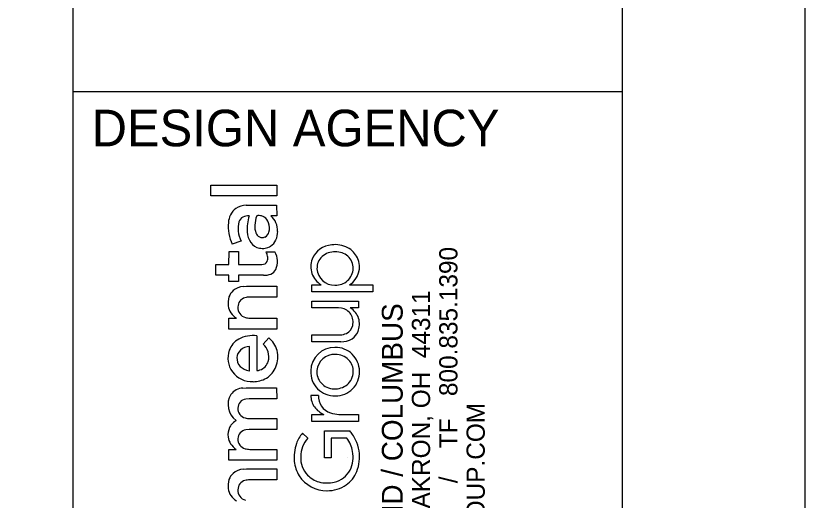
# Model space of a CAD drawing. Extents: x -0.5 to 34, y 0 to 22.
# Drawn here: x 31.843 to 34, y 3.382 to 4.707 of the extents above; entities that cross this region are included whole.
import ezdxf

# ---------------------------------------------------------------- set-up
doc = ezdxf.new("R2010")
doc.units = 0
for name, color, linetype in [('PM_X_CL_Double_Solid', 7, 'Continuous'), ('PM_X_Edge_Line', 7, 'Continuous'), ('PM_X_Transverse_Line', 7, 'Continuous')]:
    doc.layers.add(name, color=color, linetype=linetype)

msp = doc.modelspace()

# ---------------------------------------------------------------- linework, layer by layer
at = {"layer": 'PM_X_CL_Double_Solid'}
for p, q in [((32.3756, 4.2141), (32.3756, 4.244)), ((32.3756, 4.244), (32.5557, 4.244)), ((32.5557, 4.244), (32.5557, 4.2141)), ((32.5557, 4.2141), (32.3756, 4.2141)), ((32.4727, 4.189), (32.5555, 4.1892)), ((32.5555, 4.1892), (32.5557, 4.1596)), ((32.5557, 4.1596), (32.5397, 4.1596)), ((32.4582, 4.0904), (32.4343, 4.0823)), ((32.4254, 4.027), (32.4255, 4.0621)), ((32.4255, 4.0621), (32.4511, 4.0621)), ((32.4511, 4.0621), (32.4512, 4.027)), ((32.527, 4.0616), (32.5511, 4.0616)), ((32.3896, 3.9972), (32.3896, 4.027)), ((32.3896, 4.027), (32.4254, 4.027)), ((32.4512, 4.027), (32.515, 4.027)), ((32.515, 4.027), (32.52, 4.0275)), ((32.4254, 3.9972), (32.3896, 3.9972)), ((32.4254, 3.9807), (32.4254, 3.9972)), ((32.5197, 3.9972), (32.4511, 3.9972)), ((32.4511, 3.9972), (32.4511, 3.9807)), ((32.4511, 3.9807), (32.4254, 3.9807)), ((32.6515, 3.9521), (32.6515, 3.9711)), ((32.6515, 3.9711), (32.6771, 3.9711)), ((32.7549, 3.9713), (32.8186, 3.9711)), ((32.8186, 3.9711), (32.8184, 3.9521)), ((32.4644, 3.9669), (32.4729, 3.9673)), ((32.4729, 3.9673), (32.5557, 3.9673)), ((32.5557, 3.9673), (32.5557, 3.9375)), ((32.8184, 3.9521), (32.6515, 3.9521)), ((32.5557, 3.9375), (32.4814, 3.9375)), ((32.6515, 3.908), (32.6515, 3.9267)), ((32.6515, 3.9267), (32.7791, 3.9266)), ((32.7791, 3.9266), (32.7791, 3.908)), ((32.7249, 3.908), (32.6515, 3.908)), ((32.7328, 3.9073), (32.7249, 3.908)), ((32.7791, 3.908), (32.7569, 3.908)), ((32.4254, 3.8503), (32.4254, 3.8802)), ((32.4254, 3.8802), (32.4455, 3.8802)), ((32.4822, 3.8802), (32.5557, 3.8802)), ((32.5557, 3.8802), (32.5557, 3.8504)), ((32.5557, 3.8504), (32.4254, 3.8503)), ((32.5011, 3.8321), (32.5012, 3.7366)), ((32.5188, 3.8093), (32.5342, 3.8266)), ((32.6515, 3.8344), (32.7291, 3.8345)), ((32.6517, 3.8154), (32.6515, 3.8344)), ((32.4814, 3.7364), (32.4814, 3.803)), ((32.7307, 3.8154), (32.6517, 3.8154)), ((32.4802, 3.7363), (32.4814, 3.7364)), ((32.4633, 3.6891), (32.4726, 3.6897)), ((32.4726, 3.6897), (32.5556, 3.6897)), ((32.5556, 3.6897), (32.5557, 3.6598)), ((32.6493, 3.6691), (32.6698, 3.6691)), ((32.4806, 3.6598), (32.471, 3.6588)), ((32.5557, 3.6598), (32.4806, 3.6598)), ((32.4822, 3.6055), (32.5557, 3.6055)), ((32.5557, 3.6055), (32.5557, 3.5757)), ((32.6515, 3.598), (32.6515, 3.617)), ((32.6515, 3.617), (32.6848, 3.617)), ((32.726, 3.617), (32.7791, 3.617)), ((32.7791, 3.617), (32.779, 3.598)), ((32.4444, 3.5992), (32.4446, 3.6007)), ((32.779, 3.598), (32.6515, 3.598)), ((32.4809, 3.5757), (32.4714, 3.5747)), ((32.5557, 3.5757), (32.4809, 3.5757)), ((32.6264, 3.5655), (32.6411, 3.5524)), ((32.6868, 3.5718), (32.7552, 3.5719)), ((32.6868, 3.4978), (32.6868, 3.5718)), ((32.7045, 3.5524), (32.7043, 3.4978)), ((32.7474, 3.5523), (32.7045, 3.5524)), ((32.4254, 3.4915), (32.4254, 3.5214)), ((32.4254, 3.5214), (32.4451, 3.5214)), ((32.4821, 3.5214), (32.5557, 3.5214)), ((32.5557, 3.5214), (32.5557, 3.4916)), ((32.7043, 3.4978), (32.6868, 3.4978)), ((32.75, 3.5), (32.75, 3.5)), ((32.5557, 3.4916), (32.4254, 3.4915)), ((32.4644, 3.4674), (32.4729, 3.4678)), ((32.4729, 3.4678), (32.5557, 3.4678)), ((32.5557, 3.4678), (32.5557, 3.438)), ((32.5557, 3.438), (32.4814, 3.438))]:
    msp.add_line(p, q, dxfattribs=at)
msp.add_lwpolyline([(32.3756, 4.2141), (32.3756, 4.244), (32.5557, 4.244), (32.5557, 4.2141)], close=True, dxfattribs=at)
for points in [[(32.4727, 4.189), (32.5555, 4.1892), (32.5557, 4.1596)], [(32.5557, 4.1596), (32.5397, 4.1596)], [(32.4582, 4.0904), (32.4343, 4.0823)], [(32.5197, 3.9972), (32.4511, 3.9972), (32.4511, 3.9807), (32.4254, 3.9807), (32.4254, 3.9972), (32.3896, 3.9972), (32.3896, 4.027), (32.4254, 4.027), (32.4255, 4.0621), (32.4511, 4.0621), (32.4512, 4.027), (32.515, 4.027), (32.52, 4.0275)], [(32.527, 4.0616), (32.5511, 4.0616)], [(32.7549, 3.9713), (32.8186, 3.9711), (32.8184, 3.9521), (32.6515, 3.9521)], [(32.6515, 3.9521), (32.6515, 3.9711), (32.6771, 3.9711)], [(32.4644, 3.9669), (32.4729, 3.9673), (32.5557, 3.9673), (32.5557, 3.9375), (32.4814, 3.9375)], [(32.7328, 3.9073), (32.7249, 3.908), (32.6515, 3.908), (32.6515, 3.9267), (32.7791, 3.9266), (32.7791, 3.908), (32.7569, 3.908)], [(32.4254, 3.8503), (32.4254, 3.8802), (32.4455, 3.8802)], [(32.4822, 3.8802), (32.5557, 3.8802), (32.5557, 3.8504), (32.4254, 3.8503)], [(32.5011, 3.8321), (32.5012, 3.7366)], [(32.5188, 3.8093), (32.5342, 3.8266)], [(32.7307, 3.8154), (32.6517, 3.8154), (32.6515, 3.8344), (32.7291, 3.8345)], [(32.4802, 3.7363), (32.4814, 3.7364), (32.4814, 3.803)], [(32.4633, 3.6891), (32.4726, 3.6897), (32.5556, 3.6897), (32.5557, 3.6598), (32.4806, 3.6598), (32.471, 3.6588)], [(32.6493, 3.6691), (32.6698, 3.6691)], [(32.4822, 3.6055), (32.5557, 3.6055), (32.5557, 3.5757), (32.4809, 3.5757), (32.4714, 3.5747)], [(32.6515, 3.598), (32.6515, 3.617), (32.6848, 3.617)], [(32.726, 3.617), (32.7791, 3.617), (32.779, 3.598), (32.6515, 3.598)], [(32.4444, 3.5992), (32.4446, 3.6007)], [(32.6264, 3.5655), (32.6411, 3.5524)], [(32.7474, 3.5523), (32.7045, 3.5524), (32.7043, 3.4978), (32.6868, 3.4978), (32.6868, 3.5718), (32.7552, 3.5719)], [(32.4254, 3.4915), (32.4254, 3.5214), (32.4451, 3.5214)], [(32.4821, 3.5214), (32.5557, 3.5214), (32.5557, 3.4916), (32.4254, 3.4915)], [(32.4644, 3.4674), (32.4729, 3.4678), (32.5557, 3.4678), (32.5557, 3.438), (32.4814, 3.438)]]:
    msp.add_lwpolyline(points, dxfattribs=at)
for centre, radius, start, end in [((32.4745, 4.1326), 0.0565, 91.8942, 122.6317), ((32.4745, 4.1326), 0.0565, 91.8942, 122.6317), ((32.4685, 4.1447), 0.043, 124.537, 155.6594), ((32.4685, 4.1447), 0.043, 124.537, 155.6594), ((32.4882, 4.1361), 0.0646, 155.9764, 175.3149), ((32.4882, 4.1361), 0.0646, 155.9764, 175.3149), ((32.5076, 4.1265), 0.0576, 163.1369, 188.1675), ((32.5076, 4.1265), 0.0576, 163.1369, 188.1675), ((32.4753, 4.1356), 0.024, 119.4252, 161.6629), ((32.4753, 4.1356), 0.024, 119.4252, 161.6629), ((32.4779, 4.1278), 0.0321, 85.3802, 116.6222), ((32.4779, 4.1278), 0.0321, 85.3802, 116.6222), ((32.5879, 4.1251), 0.1129, 162.0821, 184.5285), ((32.5879, 4.1251), 0.1129, 162.0821, 184.5285), ((32.5801, 4.1313), 0.0841, 159.8366, 178.0362), ((32.5801, 4.1313), 0.0841, 159.8366, 178.0362), ((32.5051, 4.1074), 0.053, 79.6696, 94.2322), ((32.5051, 4.1074), 0.053, 79.6696, 94.2322), ((32.5089, 4.1364), 0.0238, 56.8913, 76.2149), ((32.5089, 4.1364), 0.0238, 56.8913, 76.2149), ((32.5052, 4.1318), 0.0297, 17.5984, 55.7282), ((32.5052, 4.1318), 0.0297, 17.5984, 55.7282), ((32.5055, 4.1191), 0.0529, 358.0746, 49.762), ((32.5055, 4.1191), 0.0529, 358.0746, 49.762), ((32.5364, 4.1308), 0.113, 174.6101, 205.3899), ((32.5364, 4.1308), 0.113, 174.6101, 205.3899), ((32.5466, 4.1303), 0.0506, 175.5903, 199.8857), ((32.5466, 4.1303), 0.0506, 175.5903, 199.8857), ((32.4916, 4.1264), 0.0443, 345.9408, 18.9919), ((32.4916, 4.1264), 0.0443, 345.9408, 18.9919), ((32.5473, 4.1297), 0.0973, 186.7598, 203.7981), ((32.5473, 4.1297), 0.0973, 186.7598, 203.7981), ((32.5328, 4.1187), 0.0575, 182.5676, 213.7144), ((32.5328, 4.1187), 0.0575, 182.5676, 213.7144), ((32.5164, 4.1189), 0.0184, 198.2844, 293.3081), ((32.5164, 4.1189), 0.0184, 198.2844, 293.3081), ((32.5152, 4.1199), 0.0199, 295.2883, 347.4639), ((32.5152, 4.1199), 0.0199, 295.2883, 347.4639), ((32.5019, 4.1168), 0.0566, 336.016, 0.5951), ((32.5019, 4.1168), 0.0566, 336.016, 0.5951), ((32.5149, 4.1078), 0.0366, 215.0668, 259.8133), ((32.5149, 4.1078), 0.0366, 215.0668, 259.8133), ((32.5175, 4.1097), 0.0394, 303.4436, 336.18), ((32.5175, 4.1097), 0.0394, 303.4436, 336.18), ((32.7108, 4.0182), 0.0624, 93.9866, 158.3119), ((32.7108, 4.0182), 0.0624, 93.9866, 158.3119), ((32.7156, 4.0065), 0.0746, 62.6889, 97.0135), ((32.7156, 4.0065), 0.0746, 62.6889, 97.0135), ((32.5175, 4.1131), 0.0423, 257.5256, 300.882), ((32.5175, 4.1131), 0.0423, 257.5256, 300.882), ((32.4863, 4.042), 0.0452, 10.1545, 25.723), ((32.4863, 4.042), 0.0452, 10.1545, 25.723), ((32.503, 4.0351), 0.0549, 336.589, 28.8991), ((32.503, 4.0351), 0.0549, 336.589, 28.8991), ((32.7138, 4.0102), 0.0513, 87.8965, 131.1812), ((32.7138, 4.0102), 0.0513, 87.8965, 131.1812), ((32.7175, 4.0102), 0.0513, 49.9089, 92.0363), ((32.7175, 4.0102), 0.0513, 49.9089, 92.0363), ((32.7212, 4.0191), 0.0608, 25.0657, 61.9602), ((32.7212, 4.0191), 0.0608, 25.0657, 61.9602), ((32.5184, 4.04), 0.0126, 277.6142, 353.7918), ((32.5184, 4.04), 0.0126, 277.6142, 353.7918), ((32.4957, 4.0436), 0.0356, 351.914, 10.2059), ((32.4957, 4.0436), 0.0356, 351.914, 10.2059), ((32.707, 4.0202), 0.0581, 158.656, 198.171), ((32.707, 4.0202), 0.0581, 158.656, 198.171), ((32.7092, 4.0167), 0.0434, 132.3289, 182.0949), ((32.7092, 4.0167), 0.0434, 132.3289, 182.0949), ((32.7215, 4.0173), 0.0433, 358.0487, 47.9447), ((32.7215, 4.0173), 0.0433, 358.0487, 47.9447), ((32.7245, 4.02), 0.0574, 301.9776, 25.6418), ((32.7245, 4.02), 0.0574, 301.9776, 25.6418), ((32.5291, 4.0261), 0.0275, 292.6889, 332.0598), ((32.5291, 4.0261), 0.0275, 292.6889, 332.0598), ((32.7135, 4.0181), 0.0478, 183.5974, 271.7045), ((32.7135, 4.0181), 0.0478, 183.5974, 271.7045), ((32.7172, 4.018), 0.0477, 267.3149, 357.4019), ((32.7172, 4.018), 0.0477, 267.3149, 357.4019), ((32.5209, 4.0486), 0.0514, 268.6727, 291.5235), ((32.5209, 4.0486), 0.0514, 268.6727, 291.5235), ((32.7103, 4.0243), 0.0627, 200.8399, 238.0162), ((32.7103, 4.0243), 0.0627, 200.8399, 238.0162), ((32.4635, 3.9255), 0.0402, 132.2238, 161.6823), ((32.4635, 3.9255), 0.0402, 132.2238, 161.6823), ((32.4687, 3.9172), 0.0499, 94.9706, 130.2248), ((32.4687, 3.9172), 0.0499, 94.9706, 130.2248), ((32.4787, 3.9211), 0.056, 162.274, 187.7917), ((32.4787, 3.9211), 0.056, 162.274, 187.7917), ((32.4748, 3.9116), 0.025, 103.6868, 182.214), ((32.4748, 3.9116), 0.025, 103.6868, 182.214), ((32.4811, 3.8915), 0.046, 89.6051, 105.3303), ((32.4811, 3.8915), 0.046, 89.6051, 105.3303), ((32.4703, 3.9209), 0.0476, 188.9646, 238.6987), ((32.4703, 3.9209), 0.0476, 188.9646, 238.6987), ((32.4774, 3.9085), 0.0276, 175.5844, 255.1382), ((32.4774, 3.9085), 0.0276, 175.5844, 255.1382), ((32.7271, 3.87), 0.0377, 33.5008, 81.3295), ((32.7271, 3.87), 0.0377, 33.5008, 81.3295), ((32.7324, 3.8648), 0.0496, 17.6221, 60.3897), ((32.7324, 3.8648), 0.0496, 17.6221, 60.3897), ((32.7241, 3.8695), 0.0405, 346.5618, 31.7539), ((32.7241, 3.8695), 0.0405, 346.5618, 31.7539), ((32.4818, 3.9224), 0.0421, 254.0891, 270.5284), ((32.4818, 3.9224), 0.0421, 254.0891, 270.5284), ((32.7234, 3.8641), 0.0584, 339.162, 15.6148), ((32.7234, 3.8641), 0.0584, 339.162, 15.6148), ((32.7337, 3.8662), 0.0304, 294.6321, 348.4863), ((32.7337, 3.8662), 0.0304, 294.6321, 348.4863), ((32.739, 3.859), 0.042, 303.1039, 338.1561), ((32.739, 3.859), 0.042, 303.1039, 338.1561), ((32.4789, 3.7737), 0.0558, 118.8294, 160.6224), ((32.4789, 3.7737), 0.0558, 118.8294, 160.6224), ((32.4918, 3.7487), 0.0839, 83.6212, 118.2845), ((32.4918, 3.7487), 0.0839, 83.6212, 118.2845), ((32.494, 3.7763), 0.0644, 13.5328, 51.3627), ((32.494, 3.7763), 0.0644, 13.5328, 51.3627), ((32.7275, 3.8808), 0.0463, 271.952, 294.0894), ((32.7275, 3.8808), 0.0463, 271.952, 294.0894), ((32.7321, 3.8726), 0.0571, 268.627, 301.4778), ((32.7321, 3.8726), 0.0571, 268.627, 301.4778), ((32.4844, 3.7607), 0.0424, 94.0131, 130.8806), ((32.4844, 3.7607), 0.0424, 94.0131, 130.8806), ((32.4803, 3.7702), 0.0549, 19.0387, 45.4432), ((32.4803, 3.7702), 0.0549, 19.0387, 45.4432), ((32.7143, 3.7348), 0.0655, 89.4821, 178.7775), ((32.7143, 3.7348), 0.0655, 89.4821, 178.7775), ((32.7158, 3.7341), 0.0662, 0.4227, 90.7613), ((32.7158, 3.7341), 0.0662, 0.4227, 90.7613), ((32.487, 3.7707), 0.0644, 160.5214, 215.7815), ((32.487, 3.7707), 0.0644, 160.5214, 215.7815), ((32.477, 3.7709), 0.0298, 132.9855, 177.1802), ((32.477, 3.7709), 0.0298, 132.9855, 177.1802), ((32.4872, 3.7743), 0.047, 344.6072, 17.0067), ((32.4872, 3.7743), 0.047, 344.6072, 17.0067), ((32.4829, 3.7738), 0.0758, 339.3543, 13.3771), ((32.4829, 3.7738), 0.0758, 339.3543, 13.3771), ((32.714, 3.7324), 0.0485, 87.6883, 175.017), ((32.714, 3.7324), 0.0485, 87.6883, 175.017), ((32.7166, 3.7304), 0.0505, 44.912, 90.7591), ((32.7166, 3.7304), 0.0505, 44.912, 90.7591), ((32.4782, 3.7697), 0.0311, 175.0014, 223.2876), ((32.4782, 3.7697), 0.0311, 175.0014, 223.2876), ((32.499, 3.7718), 0.035, 288.0108, 343.5536), ((32.499, 3.7718), 0.035, 288.0108, 343.5536), ((32.7196, 3.7345), 0.0455, 358.3228, 43.8349), ((32.7196, 3.7345), 0.0455, 358.3228, 43.8349), ((32.4891, 3.7752), 0.0687, 217.7434, 271.6561), ((32.4891, 3.7752), 0.0687, 217.7434, 271.6561), ((32.4855, 3.7783), 0.0423, 225.0645, 262.797), ((32.4855, 3.7783), 0.0423, 225.0645, 262.797), ((32.5013, 3.7568), 0.0202, 269.7004, 294.8729), ((32.5013, 3.7568), 0.0202, 269.7004, 294.8729), ((32.4955, 3.7698), 0.0626, 300.9439, 338.7322), ((32.4955, 3.7698), 0.0626, 300.9439, 338.7322), ((32.7148, 3.7334), 0.0661, 177.5373, 270.9452), ((32.7148, 3.7334), 0.0661, 177.5373, 270.9452), ((32.7108, 3.7331), 0.0453, 175.5147, 221.4205), ((32.7108, 3.7331), 0.0453, 175.5147, 221.4205), ((32.7167, 3.7327), 0.0654, 269.3083, 1.6791), ((32.7167, 3.7327), 0.0654, 269.3083, 1.6791), ((32.7193, 3.7337), 0.0457, 308.9038, 359.3095), ((32.7193, 3.7337), 0.0457, 308.9038, 359.3095), ((32.492, 3.777), 0.0706, 269.2053, 300.3357), ((32.492, 3.777), 0.0706, 269.2053, 300.3357), ((32.4664, 3.644), 0.0452, 93.9112, 142.3072), ((32.4664, 3.644), 0.0452, 93.9112, 142.3072), ((32.714, 3.7373), 0.0505, 222.6626, 268.3733), ((32.714, 3.7373), 0.0505, 222.6626, 268.3733), ((32.7157, 3.7386), 0.0518, 266.5531, 308.6725), ((32.7157, 3.7386), 0.0518, 266.5531, 308.6725), ((32.4759, 3.6437), 0.0532, 148.2879, 233.9556), ((32.4759, 3.6437), 0.0532, 148.2879, 233.9556), ((32.6988, 3.6666), 0.0495, 177.1621, 216.2802), ((32.6988, 3.6666), 0.0495, 177.1621, 216.2802), ((32.7173, 3.6664), 0.0476, 176.7699, 252.1504), ((32.7173, 3.6664), 0.0476, 176.7699, 252.1504), ((32.4738, 3.635), 0.024, 96.7576, 181.6251), ((32.4738, 3.635), 0.024, 96.7576, 181.6251), ((32.4758, 3.6324), 0.026, 175.8157, 256.1672), ((32.4758, 3.6324), 0.026, 175.8157, 256.1672), ((32.7098, 3.6755), 0.0637, 216.9153, 246.8862), ((32.7098, 3.6755), 0.0637, 216.9153, 246.8862), ((32.4817, 3.6505), 0.045, 254.3463, 270.6103), ((32.4817, 3.6505), 0.045, 254.3463, 270.6103), ((32.7269, 3.6917), 0.0747, 251.1388, 269.3469), ((32.7269, 3.6917), 0.0747, 251.1388, 269.3469), ((32.4714, 3.5612), 0.0488, 156.0638, 187.3493), ((32.4714, 3.5612), 0.0488, 156.0638, 187.3493), ((32.4619, 3.5645), 0.0387, 139.5245, 154.847), ((32.4619, 3.5645), 0.0387, 139.5245, 154.847), ((32.4638, 3.5627), 0.0414, 117.9163, 139.243), ((32.4638, 3.5627), 0.0414, 117.9163, 139.243), ((32.4742, 3.5506), 0.0243, 96.5532, 179.949), ((32.4742, 3.5506), 0.0243, 96.5532, 179.949), ((32.7016, 3.5019), 0.0986, 139.7948, 159.137), ((32.7016, 3.5019), 0.0986, 139.7948, 159.137), ((32.725, 3.5394), 0.0444, 30.9891, 47.161), ((32.725, 3.5394), 0.0444, 30.9891, 47.161), ((32.6709, 3.5002), 0.1111, 25.3031, 33.9618), ((32.6709, 3.5002), 0.1111, 25.3031, 33.9618), ((32.4646, 3.5597), 0.0418, 186.5579, 213.3885), ((32.4646, 3.5597), 0.0418, 186.5579, 213.3885), ((32.4761, 3.5486), 0.0263, 175.722, 255.7863), ((32.4761, 3.5486), 0.0263, 175.722, 255.7863), ((32.699, 3.5008), 0.0775, 138.258, 179.7006), ((32.699, 3.5008), 0.0775, 138.258, 179.7006), ((32.6789, 3.501), 0.0856, 10.0751, 36.8319), ((32.6789, 3.501), 0.0856, 10.0751, 36.8319), ((32.6704, 3.4999), 0.1117, 8.8034, 25.3348), ((32.6704, 3.4999), 0.1117, 8.8034, 25.3348), ((32.4789, 3.5708), 0.0598, 214.7043, 235.6872), ((32.4789, 3.5708), 0.0598, 214.7043, 235.6872), ((32.4819, 3.5652), 0.0438, 253.6672, 270.1498), ((32.4819, 3.5652), 0.0438, 253.6672, 270.1498), ((32.7187, 3.4997), 0.1154, 161.1438, 185.6281), ((32.7187, 3.4997), 0.1154, 161.1438, 185.6281), ((32.6756, 3.4998), 0.1065, 338.2887, 9.2855), ((32.6756, 3.4998), 0.1065, 338.2887, 9.2855), ((32.6881, 3.4973), 0.0668, 176.6658, 223.6912), ((32.6881, 3.4973), 0.0668, 176.6658, 223.6912), ((32.6842, 3.5006), 0.0804, 333.4669, 11.0367), ((32.6842, 3.5006), 0.0804, 333.4669, 11.0367), ((32.6934, 3.497), 0.0899, 185.5077, 212.0129), ((32.6934, 3.497), 0.0899, 185.5077, 212.0129), ((32.4635, 3.426), 0.0402, 132.2238, 161.6823), ((32.4635, 3.426), 0.0402, 132.2238, 161.6823), ((32.4687, 3.4177), 0.0499, 94.9706, 130.2248), ((32.4687, 3.4177), 0.0499, 94.9706, 130.2248), ((32.6987, 3.4955), 0.0652, 282.8815, 331.8147), ((32.6987, 3.4955), 0.0652, 282.8815, 331.8147), ((32.6984, 3.4917), 0.0824, 305.0306, 337.6757), ((32.6984, 3.4917), 0.0824, 305.0306, 337.6757), ((32.4787, 3.4216), 0.056, 162.274, 187.7917), ((32.4787, 3.4216), 0.056, 162.274, 187.7917), ((32.4748, 3.4121), 0.025, 103.6868, 182.214), ((32.4748, 3.4121), 0.025, 103.6868, 182.214), ((32.4811, 3.392), 0.046, 89.6051, 105.3303), ((32.4811, 3.392), 0.046, 89.6051, 105.3303), ((32.6921, 3.4975), 0.0891, 212.7022, 270.714), ((32.6921, 3.4975), 0.0891, 212.7022, 270.714), ((32.6905, 3.5001), 0.0704, 224.0215, 253.88), ((32.6905, 3.5001), 0.0704, 224.0215, 253.88), ((32.6932, 3.5125), 0.0831, 254.4535, 283.9512), ((32.6932, 3.5125), 0.0831, 254.4535, 283.9512), ((32.4703, 3.4214), 0.0476, 188.9646, 238.6987), ((32.4703, 3.4214), 0.0476, 188.9646, 238.6987), ((32.4774, 3.409), 0.0276, 175.5844, 255.1382), ((32.4774, 3.409), 0.0276, 175.5844, 255.1382), ((32.6943, 3.4998), 0.0914, 269.3273, 304.1963), ((32.6943, 3.4998), 0.0914, 269.3273, 304.1963)]:
    msp.add_arc(centre, radius, start, end, dxfattribs=at)
at = {"layer": 'PM_X_Edge_Line'}
msp.add_lwpolyline([(0, 0), (34, 0), (34, 22), (0, 22)], close=True, dxfattribs=at)
at = {"layer": 'PM_X_Transverse_Line'}
for p, q in [((32, 0.5), (32, 21.5)), ((32, 4.5), (33.5, 4.5))]:
    msp.add_line(p, q, dxfattribs=at)
msp.add_lwpolyline([(1.5, 21.5), (33.5, 21.5), (33.5, 0.5), (1.5, 0.5)], close=True, dxfattribs=at)

# ---------------------------------------------------------------- texts
at = {"layer": 'PM_X_CL_Double_Solid'}
msp.add_text('DESIGN AGENCY', height=0.1, dxfattribs=at).set_placement((32.05, 4.35))
for s, height, p in [('800.835.1390', 0.049846, (33.0497, 3.6671)), ('450 GRANT ST., AKRON, OH  44311', 0.049846, (32.9749, 2.8374)), ('AKRON / CLEVELAND / COLUMBUS', 0.056969, (32.9001, 2.638)), ('ENVDESIGNGROUP.COM', 0.049846, (33.1244, 2.8374)), ('TF', 0.04985, (33.0497, 3.5246)), ('/  ', 0.04985, (33.0497, 3.4288))]:
    msp.add_text(s, height=height, rotation=90, dxfattribs=at).set_placement(p)

doc.saveas('drawing.dxf')
